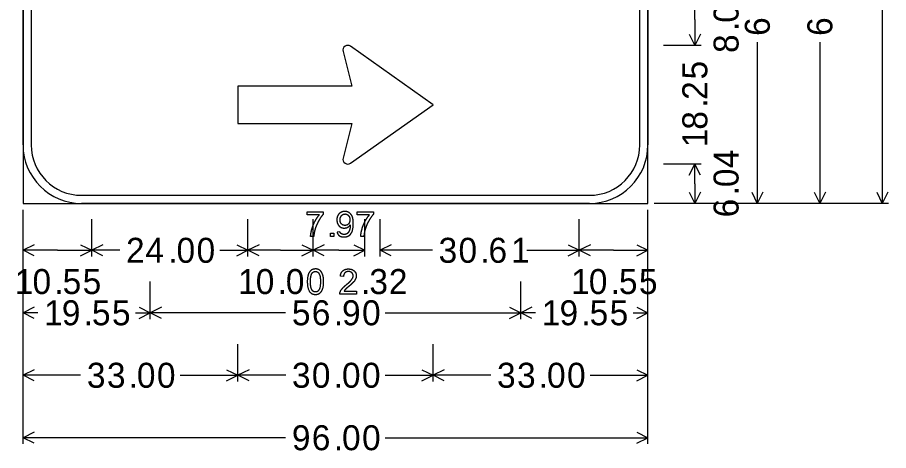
# Model space of a CAD drawing. Extents: x -11.2 to 42.9, y 0 to 22.
# Drawn here: x 25.21 to 30.79, y 15.7 to 18.47 of the extents above; entities that cross this region are included whole.
import ezdxf

# ---------------------------------------------------------------- set-up
doc = ezdxf.new("R2010")
doc.units = 0
doc.layers.add('SH_Text', color=7, linetype='Continuous')

msp = doc.modelspace()

# ---------------------------------------------------------------- linework, layer by layer
at = {"layer": 'SH_Text'}
for p, q in [((25.2476, 20.7777), (25.2476, 17.2777)), ((29.2475, 17.2777), (29.2475, 20.7777)), ((25.2476, 17.6527), (25.2476, 20.4027)), ((25.2996, 20.4027), (25.2996, 17.6527)), ((29.1955, 17.6527), (29.1955, 20.4027)), ((29.2475, 20.4027), (29.2475, 17.6527)), ((30.7475, 18.7083), (30.7475, 17.2777)), ((29.5475, 18.4564), (29.5475, 18.6231)), ((29.5475, 18.4564), (29.5475, 18.2898)), ((29.5118, 18.3613), (29.5475, 18.2898)), ((29.5833, 18.3613), (29.5475, 18.2898)), ((29.5875, 18.2898), (29.3475, 18.2898)), ((29.9475, 18.3104), (29.9475, 17.2777)), ((30.3475, 18.3104), (30.3475, 17.2777)), ((27.2964, 18.251), (27.3517, 18.0294)), ((27.8725, 17.9096), (27.3443, 18.2844)), ((27.3517, 18.0294), (26.6226, 18.0294)), ((26.6226, 18.0294), (26.6226, 17.7898)), ((27.3443, 17.5348), (27.8725, 17.9096)), ((26.6226, 17.7898), (27.3517, 17.7898)), ((27.3517, 17.7898), (27.2964, 17.5682)), ((29.5875, 17.5294), (29.3475, 17.5294)), ((29.5875, 17.5294), (29.3475, 17.5294)), ((29.5118, 17.4578), (29.5475, 17.5294)), ((29.5475, 17.4035), (29.5475, 17.5294)), ((29.5833, 17.4578), (29.5475, 17.5294)), ((29.5475, 17.4035), (29.5475, 17.2777)), ((29.5118, 17.3493), (29.5475, 17.2777)), ((29.5833, 17.3493), (29.5475, 17.2777)), ((29.9118, 17.3493), (29.9475, 17.2777)), ((29.9833, 17.3493), (29.9475, 17.2777)), ((30.3118, 17.3493), (30.3475, 17.2777)), ((30.3833, 17.3493), (30.3475, 17.2777)), ((30.7118, 17.3493), (30.7475, 17.2777)), ((30.7833, 17.3493), (30.7475, 17.2777)), ((25.6226, 17.3298), (28.8725, 17.3298)), ((25.2476, 17.2777), (29.2475, 17.2777)), ((25.2476, 15.7377), (25.2476, 17.2377)), ((28.8725, 17.2777), (25.6226, 17.2777)), ((29.2475, 15.7377), (29.2475, 17.2377)), ((30.7875, 17.2777), (29.2875, 17.2777)), ((29.5875, 17.2777), (29.3475, 17.2777)), ((29.9875, 17.2777), (29.7475, 17.2777)), ((30.3875, 17.2777), (30.1475, 17.2777)), ((25.2476, 16.9377), (25.2476, 17.1777)), ((25.6872, 16.9377), (25.6872, 17.1777)), ((26.6872, 16.9377), (26.6872, 17.1777)), ((27.1038, 16.9377), (27.1038, 17.1777)), ((27.3398, 17.1735), (27.3398, 17.1735)), ((27.4359, 16.9377), (27.4359, 17.1777)), ((27.5325, 16.9377), (27.5325, 17.1777)), ((28.8079, 16.9377), (28.8079, 17.1777)), ((28.8079, 16.9377), (28.8079, 17.1777)), ((29.2475, 16.9377), (29.2475, 17.1777)), ((27.1086, 17.0659), (27.0884, 17.0659)), ((27.2762, 17.096), (27.2573, 17.0942)), ((27.4294, 17.0659), (27.4092, 17.0659)), ((25.3191, 17.0135), (25.2476, 16.9777)), ((25.6156, 17.0135), (25.6872, 16.9777)), ((25.7587, 17.0135), (25.6872, 16.9777)), ((26.6156, 17.0135), (26.6872, 16.9777)), ((26.7587, 17.0135), (26.6872, 16.9777)), ((27.0323, 17.0135), (27.1038, 16.9777)), ((27.1754, 17.0135), (27.1038, 16.9777)), ((27.3643, 17.0135), (27.4359, 16.9777)), ((27.6041, 17.0135), (27.5325, 16.9777)), ((28.7364, 17.0135), (28.8079, 16.9777)), ((28.8795, 17.0135), (28.8079, 16.9777)), ((29.176, 17.0135), (29.2475, 16.9777)), ((25.4674, 16.9777), (25.2476, 16.9777)), ((25.3191, 16.9419), (25.2476, 16.9777)), ((25.4674, 16.9777), (25.6872, 16.9777)), ((25.6156, 16.9419), (25.6872, 16.9777)), ((25.867, 16.9777), (25.6872, 16.9777)), ((25.7587, 16.9419), (25.6872, 16.9777)), ((26.5074, 16.9777), (26.6872, 16.9777)), ((26.6156, 16.9419), (26.6872, 16.9777)), ((26.8955, 16.9777), (26.6872, 16.9777)), ((26.7587, 16.9419), (26.6872, 16.9777)), ((26.8955, 16.9777), (27.1038, 16.9777)), ((27.0323, 16.9419), (27.1038, 16.9777)), ((27.2698, 16.9777), (27.1038, 16.9777)), ((27.1754, 16.9419), (27.1038, 16.9777)), ((27.2698, 16.9777), (27.4359, 16.9777)), ((27.3643, 16.9419), (27.4359, 16.9777)), ((27.8676, 16.9777), (27.5325, 16.9777)), ((27.6041, 16.9419), (27.5325, 16.9777)), ((28.4728, 16.9777), (28.8079, 16.9777)), ((28.7364, 16.9419), (28.8079, 16.9777)), ((29.0277, 16.9777), (28.8079, 16.9777)), ((28.8795, 16.9419), (28.8079, 16.9777)), ((29.0277, 16.9777), (29.2475, 16.9777)), ((29.176, 16.9419), (29.2475, 16.9777)), ((27.2992, 16.81), (27.279, 16.812)), ((25.2476, 16.5377), (25.2476, 16.7777)), ((26.0621, 16.5377), (26.0621, 16.7777)), ((27.0672, 16.7766), (27.0672, 16.7766)), ((27.0874, 16.7766), (27.0874, 16.7766)), ((28.433, 16.5377), (28.433, 16.7777)), ((28.433, 16.5377), (28.433, 16.7777)), ((29.2475, 16.5377), (29.2475, 16.7777)), ((25.3191, 16.6135), (25.2476, 16.5777)), ((25.343, 16.5777), (25.2476, 16.5777)), ((25.3191, 16.5419), (25.2476, 16.5777)), ((25.9666, 16.5777), (26.0621, 16.5777)), ((25.9905, 16.6135), (26.0621, 16.5777)), ((25.9905, 16.5419), (26.0621, 16.5777)), ((26.1336, 16.6135), (26.0621, 16.5777)), ((26.9286, 16.5777), (26.0621, 16.5777)), ((26.1336, 16.5419), (26.0621, 16.5777)), ((27.5665, 16.5777), (28.433, 16.5777)), ((28.3615, 16.6135), (28.433, 16.5777)), ((28.3615, 16.5419), (28.433, 16.5777)), ((28.5046, 16.6135), (28.433, 16.5777)), ((28.5285, 16.5777), (28.433, 16.5777)), ((28.5046, 16.5419), (28.433, 16.5777)), ((29.1521, 16.5777), (29.2475, 16.5777)), ((29.176, 16.6135), (29.2475, 16.5777)), ((29.176, 16.5419), (29.2475, 16.5777)), ((25.2476, 16.1377), (25.2476, 16.3777)), ((26.6226, 16.1377), (26.6226, 16.3777)), ((27.8725, 16.1377), (27.8725, 16.3777)), ((27.8725, 16.1377), (27.8725, 16.3777)), ((29.2475, 16.1377), (29.2475, 16.3777)), ((25.3191, 16.2135), (25.2476, 16.1777)), ((25.6165, 16.1777), (25.2476, 16.1777)), ((25.3191, 16.1419), (25.2476, 16.1777)), ((26.2536, 16.1777), (26.6226, 16.1777)), ((26.551, 16.2135), (26.6226, 16.1777)), ((26.551, 16.1419), (26.6226, 16.1777)), ((26.6941, 16.2135), (26.6226, 16.1777)), ((26.929, 16.1777), (26.6226, 16.1777)), ((26.6941, 16.1419), (26.6226, 16.1777)), ((27.5661, 16.1777), (27.8725, 16.1777)), ((27.801, 16.2135), (27.8725, 16.1777)), ((27.801, 16.1419), (27.8725, 16.1777)), ((27.9441, 16.2135), (27.8725, 16.1777)), ((28.2415, 16.1777), (27.8725, 16.1777)), ((27.9441, 16.1419), (27.8725, 16.1777)), ((28.8786, 16.1777), (29.2475, 16.1777)), ((29.176, 16.2135), (29.2475, 16.1777)), ((29.176, 16.1419), (29.2475, 16.1777)), ((25.3191, 15.8135), (25.2476, 15.7777)), ((29.176, 15.8135), (29.2475, 15.7777)), ((26.9286, 15.7777), (25.2476, 15.7777)), ((25.3191, 15.7419), (25.2476, 15.7777)), ((27.5665, 15.7777), (29.2475, 15.7777)), ((29.176, 15.7419), (29.2475, 15.7777))]:
    msp.add_line(p, q, dxfattribs=at)
for points in [[(27.1443, 17.2049), (27.066, 17.2049), (27.066, 17.2238), (27.1696, 17.2238), (27.1696, 17.2085)], [(27.4652, 17.2049), (27.3869, 17.2049), (27.3869, 17.2238), (27.4904, 17.2238), (27.4904, 17.2085)], [(27.3026, 16.7166), (27.381, 16.7166), (27.381, 16.6977), (27.2753, 16.6977)]]:
    msp.add_lwpolyline(points, dxfattribs=at)
msp.add_lwpolyline([(27.2372, 17.0882), (27.2372, 17.0659), (27.2147, 17.0659), (27.2147, 17.0882)], close=True, dxfattribs=at)
for centre, radius, start, end in [((27.3267, 18.2585), 0.0312, 55.8573, 194.0168), ((25.6226, 17.6527), 0.375, 180, 270), ((25.6226, 17.6527), 0.3229, 180, 270), ((28.8725, 17.6527), 0.375, 270, 0), ((28.8725, 17.6527), 0.3229, 270, 0), ((27.3267, 17.5606), 0.0312, 165.9832, 304.1427)]:
    msp.add_arc(centre, radius, start, end, dxfattribs=at)
for points in [[(27.1161, 17.163), (27.1229, 17.1755), (27.1298, 17.1859)], [(27.1298, 17.1859), (27.1368, 17.1964), (27.1443, 17.2049)], [(27.1696, 17.2085), (27.1541, 17.192), (27.1392, 17.1653)], [(27.2707, 17.2116), (27.2564, 17.1967), (27.2564, 17.1725)], [(27.3068, 17.2265), (27.2849, 17.2263), (27.2707, 17.2116)], [(27.2766, 17.1718), (27.2767, 17.1871), (27.2851, 17.1981)], [(27.2851, 17.1981), (27.2944, 17.2103), (27.3091, 17.2102)], [(27.3357, 17.2179), (27.3226, 17.2266), (27.3068, 17.2265)], [(27.3091, 17.2102), (27.3234, 17.2101), (27.332, 17.1987)], [(27.332, 17.1987), (27.3398, 17.1883), (27.3398, 17.1735)], [(27.3398, 17.1735), (27.3398, 17.1582), (27.332, 17.1481)], [(27.3549, 17.1941), (27.3484, 17.2091), (27.3357, 17.2179)], [(27.3617, 17.1491), (27.3617, 17.1783), (27.3549, 17.1941)], [(27.4369, 17.163), (27.4437, 17.1755), (27.4507, 17.1859)], [(27.4507, 17.1859), (27.4577, 17.1964), (27.4652, 17.2049)], [(27.4904, 17.2085), (27.4749, 17.192), (27.4601, 17.1653)], [(27.097, 17.1158), (27.1045, 17.1413), (27.1161, 17.163)], [(27.1262, 17.1385), (27.1205, 17.1249), (27.1161, 17.1098)], [(27.1392, 17.1653), (27.1319, 17.1522), (27.1262, 17.1385)], [(27.2564, 17.1725), (27.2564, 17.1505), (27.269, 17.1357)], [(27.269, 17.1357), (27.2822, 17.1199), (27.3038, 17.1201)], [(27.2852, 17.1475), (27.2765, 17.1574), (27.2766, 17.1718)], [(27.3086, 17.1374), (27.2943, 17.1374), (27.2852, 17.1475)], [(27.3038, 17.1201), (27.3288, 17.1202), (27.342, 17.1412)], [(27.332, 17.1481), (27.3236, 17.1374), (27.3086, 17.1374)], [(27.3351, 17.0726), (27.3617, 17.0917), (27.3617, 17.1491)], [(27.3421, 17.1372), (27.3421, 17.1248), (27.3392, 17.1132)], [(27.342, 17.1412), (27.3421, 17.1403), (27.3421, 17.1393)], [(27.3421, 17.1393), (27.3421, 17.1383), (27.3421, 17.1372)], [(27.4178, 17.1158), (27.4254, 17.1413), (27.4369, 17.163)], [(27.447, 17.1385), (27.4413, 17.1249), (27.4369, 17.1098)], [(27.4601, 17.1653), (27.4527, 17.1522), (27.447, 17.1385)], [(27.0884, 17.0659), (27.0889, 17.0883), (27.097, 17.1158)], [(27.1161, 17.1098), (27.1102, 17.0897), (27.1086, 17.0659)], [(27.2573, 17.0942), (27.2587, 17.0825), (27.2716, 17.0715)], [(27.2716, 17.0715), (27.2811, 17.0634), (27.3044, 17.0634)], [(27.2854, 17.0833), (27.2774, 17.0887), (27.2762, 17.096)], [(27.3048, 17.0793), (27.2913, 17.0794), (27.2854, 17.0833)], [(27.3044, 17.0634), (27.3223, 17.0634), (27.3351, 17.0726)], [(27.3206, 17.0834), (27.3135, 17.0791), (27.3048, 17.0793)], [(27.3392, 17.1132), (27.3336, 17.0913), (27.3206, 17.0834)], [(27.4092, 17.0659), (27.4098, 17.0883), (27.4178, 17.1158)], [(27.4369, 17.1098), (27.431, 17.0897), (27.4294, 17.0659)], [(27.0904, 16.8489), (27.0672, 16.8299), (27.0672, 16.7766)], [(27.1194, 16.8583), (27.1016, 16.8582), (27.0904, 16.8489)], [(27.0975, 16.8306), (27.1055, 16.8422), (27.1192, 16.8421)], [(27.1192, 16.8421), (27.1397, 16.8419), (27.1471, 16.8174)], [(27.142, 16.8531), (27.1319, 16.8584), (27.1194, 16.8583)], [(27.168, 16.8143), (27.1603, 16.8434), (27.142, 16.8531)], [(27.279, 16.812), (27.281, 16.8344), (27.2946, 16.8464)], [(27.2946, 16.8464), (27.3081, 16.8583), (27.3309, 16.8583)], [(27.3305, 16.8421), (27.316, 16.8422), (27.3076, 16.8334)], [(27.3517, 16.8345), (27.3432, 16.8418), (27.3305, 16.8421)], [(27.3309, 16.8583), (27.352, 16.8583), (27.366, 16.8469)], [(27.366, 16.8469), (27.3808, 16.8346), (27.3808, 16.8139)], [(27.0874, 16.7766), (27.0874, 16.8162), (27.0975, 16.8306)], [(27.1471, 16.8174), (27.1514, 16.8033), (27.1514, 16.7766)], [(27.1716, 16.7766), (27.1716, 16.8006), (27.168, 16.8143)], [(27.3076, 16.8334), (27.2993, 16.8248), (27.2992, 16.81)], [(27.3441, 16.7819), (27.3606, 16.7997), (27.3606, 16.8143)], [(27.3606, 16.8143), (27.3606, 16.8269), (27.3517, 16.8345)], [(27.3808, 16.8139), (27.3808, 16.7948), (27.3638, 16.7755)], [(27.0672, 16.7766), (27.0673, 16.6951), (27.1194, 16.6952)], [(27.0917, 16.7358), (27.0874, 16.7499), (27.0874, 16.7766)], [(27.1194, 16.7111), (27.099, 16.7112), (27.0917, 16.7358)], [(27.1514, 16.7766), (27.1514, 16.7109), (27.1194, 16.7111)], [(27.1484, 16.7044), (27.1716, 16.7233), (27.1716, 16.7766)], [(27.2753, 16.6977), (27.2749, 16.7142), (27.2905, 16.7326)], [(27.2905, 16.7326), (27.2992, 16.743), (27.3162, 16.7568)], [(27.3169, 16.7331), (27.3123, 16.7288), (27.3087, 16.7247)], [(27.3162, 16.7568), (27.3261, 16.7648), (27.3331, 16.7711)], [(27.3222, 16.7378), (27.3181, 16.7343), (27.3169, 16.7331)], [(27.3335, 16.7473), (27.3263, 16.7413), (27.3222, 16.7378)], [(27.3331, 16.7711), (27.34, 16.7774), (27.3441, 16.7819)], [(27.3516, 16.7632), (27.3441, 16.7562), (27.3335, 16.7473)], [(27.3638, 16.7755), (27.3591, 16.7702), (27.3516, 16.7632)], [(27.1194, 16.6952), (27.1282, 16.6953), (27.1355, 16.6975)], [(27.1355, 16.6975), (27.1427, 16.6997), (27.1484, 16.7044)], [(27.3087, 16.7247), (27.3051, 16.7206), (27.3026, 16.7166)]]:
    msp.add_open_spline(points, degree=2, dxfattribs=at)

# ---------------------------------------------------------------- texts
for s, p in [('0', (29.8275, 18.4347)), ('6', (30.0275, 18.3504)), ('6', (30.4275, 18.3504)), ('.', (29.8275, 18.3819)), ('8', (29.8275, 18.2412)), ('5', (29.6275, 18.0717)), ('2', (29.6275, 17.941)), ('.', (29.6275, 17.8907)), ('8', (29.6275, 17.75)), ('1', (29.6275, 17.6377)), ('4', (29.8275, 17.5036)), ('0', (29.8275, 17.3822)), ('.', (29.8275, 17.3294)), ('6', (29.8275, 17.1887))]:
    msp.add_text(s, height=0.16, rotation=90, dxfattribs=at).set_placement(p)
for s, p in [('2', (25.907, 16.8977)), ('4', (26.0309, 16.8977)), ('0', (26.2303, 16.8977)), ('0', (26.3585, 16.8977)), ('3', (27.9076, 16.8977)), ('0', (28.0349, 16.8977)), ('6', (28.2268, 16.8977)), ('1', (28.3709, 16.8977)), ('.', (26.1775, 16.8977)), ('.', (28.1748, 16.8977)), ('1', (25.1955, 16.6977)), ('0', (25.3086, 16.6977)), ('5', (25.5013, 16.6977)), ('5', (25.6295, 16.6977)), ('1', (26.6241, 16.6977)), ('0', (26.7372, 16.6977)), ('0', (26.9298, 16.6977)), ('3', (27.4645, 16.6977)), ('2', (27.5893, 16.6977)), ('1', (28.7559, 16.6977)), ('0', (28.869, 16.6977)), ('5', (29.0617, 16.6977)), ('5', (29.1898, 16.6977)), ('.', (25.4485, 16.6977)), ('.', (26.8771, 16.6977)), ('.', (27.4109, 16.6977)), ('.', (29.0089, 16.6977)), ('1', (25.383, 16.4977)), ('9', (25.4961, 16.4977)), ('5', (25.6887, 16.4977)), ('5', (25.8169, 16.4977)), ('5', (26.9686, 16.4977)), ('6', (27.0959, 16.4977)), ('9', (27.2894, 16.4977)), ('0', (27.4176, 16.4977)), ('1', (28.5685, 16.4977)), ('9', (28.6816, 16.4977)), ('5', (28.8742, 16.4977)), ('5', (29.0024, 16.4977)), ('.', (25.636, 16.4977)), ('.', (27.2367, 16.4977)), ('.', (28.8214, 16.4977)), ('3', (25.6565, 16.0977)), ('3', (25.7847, 16.0977)), ('0', (25.9765, 16.0977)), ('0', (26.1047, 16.0977)), ('3', (26.969, 16.0977)), ('0', (27.0963, 16.0977)), ('0', (27.289, 16.0977)), ('0', (27.4172, 16.0977)), ('3', (28.2815, 16.0977)), ('3', (28.4097, 16.0977)), ('0', (28.6015, 16.0977)), ('0', (28.7297, 16.0977)), ('.', (25.9237, 16.0977)), ('.', (27.2362, 16.0977)), ('.', (28.5487, 16.0977)), ('9', (26.9686, 15.6977)), ('6', (27.0959, 15.6977)), ('0', (27.2894, 15.6977)), ('0', (27.4176, 15.6977)), ('.', (27.2367, 15.6977))]:
    msp.add_text(s, height=0.16, dxfattribs=at).set_placement(p)

doc.saveas('drawing.dxf')
